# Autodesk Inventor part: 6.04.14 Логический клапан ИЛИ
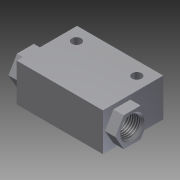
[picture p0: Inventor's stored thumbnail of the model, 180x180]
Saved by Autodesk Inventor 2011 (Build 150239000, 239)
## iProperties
Created: 2011-08
Part Number: 6.04.14 Логический клапан ИЛИ
Document SubType Name: Modeling
Designer: khramov
Density: 1 g/cm^3
Author: khramov
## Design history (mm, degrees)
sketch "Эскиз1"
  geometry: L1 (0, 0)-(50, 0); L2 (50, 0)-(50, -35); L3 (50, -35)-(0, -35); L4 (0, -35)-(0, 0)
  constraints: 8 end point, 2 parallel, 1 horizontal, 1 perpendicular
  dimensions: "d0" = 50 distance of L1.start L1.end; "d1" = 35 distance of L3.end L1.start
extrude "Выдавливание1" new body sketch "Эскиз1" distance "d2" = 22; taper "d3" = 0 deg
sketch "Эскиз2"
  geometry: L1 (0, 0)-(-22, 0) reference; L2 (-11, 1.185)-(-19.5, 6.093); L3 (-19.5, 6.093)-(-19.5, 15.907); L4 (-19.5, 15.907)-(-11, 20.815); L5 (-11, 20.815)-(-2.5, 15.907); L6 (-2.5, 15.907)-(-2.5, 6.093); L7 (-2.5, 6.093)-(-11, 1.185); 1 further point
  constraints: 12 end point, 13 other
  dimensions: "d4" = 17 distance between parallel lines of L6 L3; "d5" = 11 distance from line of point (-11, 11) L1
extrude "Выдавливание2" join sketch "Эскиз2" distance "d6" = 6; taper "d7" = 0 deg
sketch "Эскиз3"
  geometry: L1 (0, 0)-(22, 0) reference; L2 (11, 20.815)-(19.5, 15.907); L3 (19.5, 15.907)-(19.5, 6.093); L4 (19.5, 6.093)-(11, 1.185); L5 (11, 1.185)-(2.5, 6.093); L6 (2.5, 6.093)-(2.5, 15.907); L7 (2.5, 15.907)-(11, 20.815); 1 further point
  constraints: 12 end point, 13 other
  dimensions: "d8" = 17 distance between parallel lines of L6 L3; "d9" = 11 distance from line of L1 point (11, 11)
extrude "Выдавливание3" join sketch "Эскиз3" distance "d10" = 6; taper "d11" = 0 deg
sketch "Эскиз4"
  geometry: L1 (50, -35)-(0, -35) reference; L2 (7.5, -7.819)-(42.5, -7.819); L3 (0, 0)-(50, 0) reference; L4 (25, 0)-(25, -7.819); C1 r 2.75 at (7.5, -7.819); C2 r 2.75 at (42.5, -7.819)
  constraints: 4 end point, 2 centre point, 2 coincident, 2 midpoint, 1 parallel, 1 vertical
  dimensions: "d12" = 5.5 diameter of C2; "d13" = 5.5 diameter of C1; "d14" = 35 distance of L2.start L2.end
extrude "Выдавливание4" cut sketch "Эскиз4" stored distance "d15" = 6; taper "d16" = 0 deg
sketch "Эскиз5"
  geometry: L1 (50, 0)-(50, -22) reference; L2 (0, 0)-(50, 0) reference; L3 (0, -11)-(50, -11); L4 (50, 0)-(0, 0) reference; L5 (50, -22)-(0, -22) reference; L6 (25, -22)-(25, 0); 1 further point
  constraints: 4 end point, 3 midpoint, 2 perpendicular
hole "Отверстие1" sketch "Эскиз5" at (25, -11) diameter "d17" = 11.445; stored, may be unused: countersink angle "d21" = 90 deg, drill point angle "d23" = 118 deg; dims "d18" = 16, "d19" = 14, "d20" = 2, "d22" = 25
sketch "Эскиз6"
  geometry: 2 further points
hole "Отверстие2" sketch "Эскиз6" at (-11, 11) diameter "d24" = 11.445; stored, may be unused: countersink angle "d28" = 90 deg, drill point angle "d30" = 118 deg; dims "d25" = 16, "d26" = 14, "d27" = 2, "d29" = 30
sketch "Эскиз7"
  geometry: 2 further points
hole "Отверстие3" sketch "Эскиз7" at (11, 11) diameter "d31" = 11.445; stored, may be unused: countersink angle "d35" = 90 deg, drill point angle "d37" = 118 deg; dims "d32" = 16, "d33" = 14, "d34" = 2, "d36" = 35
node "Твердое тело1"
